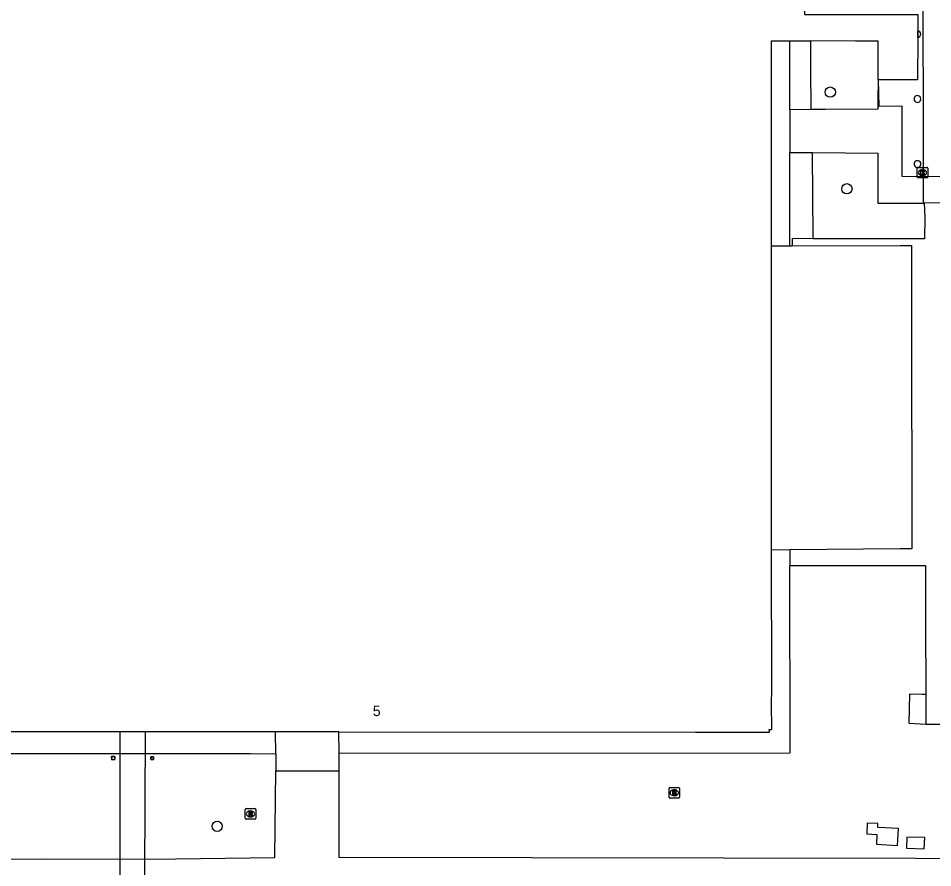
# Model space of a CAD drawing. Extents: x 161477 to 163040, y 383680 to 384868.
# Drawn here: x 161935.3 to 162022.7, y 384190.1 to 384271.2 of the extents above; entities that cross this region are included whole.
import ezdxf

# ---------------------------------------------------------------- set-up
doc = ezdxf.new("R2010")
doc.units = 0
for name, color, linetype in [('IMGEO_Boom', 7, 'Continuous'), ('IMGEO_Dek', 7, 'Continuous'), ('IMGEO_Groenvoorziening', 7, 'Continuous'), ('IMGEO_Kolk', 7, 'Continuous'), ('IMGEO_Pand', 7, 'Continuous'), ('IMGEO_Pand_nummerreeks', 7, 'Continuous'), ('IMGEO_Pand_overbouw', 7, 'Continuous'), ('IMGEO_Pijler', 7, 'Continuous'), ('IMGEO_Rijbaan_lokaal_open', 7, 'Continuous'), ('IMGEO_Rioolput', 7, 'Continuous'), ('IMGEO_Voetpad_gesloten', 7, 'Continuous'), ('IMGEO_Voetpad_op_trap', 7, 'Continuous'), ('IMGEO_Voetpad_open', 7, 'Continuous')]:
    doc.layers.add(name, color=color, linetype=linetype)

msp = doc.modelspace()

# ---------------------------------------------------------------- linework, layer by layer
at = {"layer": 'IMGEO_Boom'}
for centre in [(162012.875, 384264.123), (162014.462, 384254.892), (161954.33, 384194.04)]:
    msp.add_circle(centre, 0.489, dxfattribs=at)
at = {"layer": 'IMGEO_Dek'}
msp.add_lwpolyline([(161947.489, 384203.069), (161945.033, 384203.068), (161945.027, 384175.873), (161947.367, 384175.873)], close=True, dxfattribs=at)
at = {"layer": 'IMGEO_Groenvoorziening'}
for points in [[(162009.013, 384262.435), (162009.005, 384268.839), (162009.005, 384269.016)], [(162010.976, 384269.004), (162010.991, 384266.446), (162011.013, 384262.446)], [(162009.028, 384249.462), (162009.028, 384250.61), (162009.018, 384258.358)], [(162011.256, 384250.13), (162011.254, 384250.328), (162011.163, 384258.196), (162011.161, 384258.345)], [(161965.971, 384201.033), (162009.044, 384201.043), (162009.028, 384218.951)], [(161944.549, 384200.403), (161944.256, 384200.397), (161944.25, 384200.69), (161944.543, 384200.696), (161944.549, 384200.403)], [(161947.99, 384200.678), (161948.263, 384200.679), (161948.264, 384200.406), (161947.991, 384200.405), (161947.99, 384200.678)]]:
    msp.add_lwpolyline(points, dxfattribs=at)
at = {"layer": 'IMGEO_Kolk'}
for p, q in [((162021.174, 384256.011), (162021.174, 384256.863)), ((162021.249, 384256.937), (162022.101, 384256.937)), ((162022.175, 384256.863), (162022.175, 384256.011)), ((162022.101, 384255.937), (162021.249, 384255.937)), ((162021.685, 384256.157), (162021.66, 384256.157)), ((162021.662, 384256.717), (162021.687, 384256.717))]:
    msp.add_line(p, q, dxfattribs=at)
for points in [[(162021.174, 384256.011), (162021.174, 384256.863)], [(162021.249, 384256.937), (162022.101, 384256.937)], [(162022.175, 384256.863), (162022.175, 384256.011)], [(162022.101, 384255.937), (162021.249, 384255.937)], [(162021.495, 384256.637), (162021.618, 384256.637), (162021.618, 384256.486), (162021.748, 384256.637), (162021.912, 384256.637), (162021.766, 384256.486), (162021.919, 384256.237), (162021.767, 384256.237), (162021.682, 384256.401), (162021.618, 384256.334), (162021.618, 384256.237), (162021.495, 384256.237), (162021.495, 384256.637)]]:
    msp.add_lwpolyline(points, dxfattribs=at)
for centre, start, end in [((162021.251, 384256.861), 91.55205, 178.44795), ((162021.251, 384256.861), 91.55205, 178.44795), ((162022.099, 384256.861), 1.55205, 88.44795), ((162022.099, 384256.861), 1.55205, 88.44795), ((162021.251, 384256.013), 181.55205, 268.44795), ((162021.251, 384256.013), 181.55205, 268.44795), ((162022.099, 384256.013), 271.55205, 358.44795), ((162022.099, 384256.013), 271.55205, 358.44795)]:
    msp.add_arc(centre, 0.0765, start, end, dxfattribs=at)
for centre, major_axis, ratio, start_param, end_param in [((162021.661, 384256.437), (-0.387, 0.002), 0.722429, 4.712389, 7.853982), ((162021.686, 384256.437), (-0.39, 0.002), 0.717154, 1.570796, 4.712389)]:
    msp.add_ellipse(centre, major_axis=major_axis, ratio=ratio, start_param=start_param, end_param=end_param, dxfattribs=at)
at = {"layer": 'IMGEO_Pand'}
for points in [[(162010.435, 384272.775), (162010.425, 384271.541), (162021.222, 384271.531), (162021.226, 384269.972)], [(162021.227, 384269.341), (162021.226, 384269.972)], [(162007.258, 384249.461), (162007.258, 384250), (162007.266, 384269.027), (162009.005, 384269.016)], [(162009.005, 384269.016), (162010.976, 384269.004)], [(162017.446, 384265.289), (162017.441, 384268.979), (162015.281, 384268.977), (162010.976, 384269.004)], [(162021.227, 384269.341), (162021.217, 384265.294), (162017.446, 384265.289)], [(161959.912, 384203.067), (161949.955, 384203.074), (161947.489, 384203.069), (161945.033, 384203.068), (161931.102, 384203.074), (161931.103, 384235.656), (161931.102, 384250), (161931.102, 384256.645)], [(162007.274, 384220.411), (162007.274, 384221.561), (162007.272, 384231.847), (162007.271, 384234.348), (162007.275, 384235.638), (162007.254, 384239.224), (162007.258, 384249.461)], [(161965.955, 384203.063), (162000, 384203.041), (162007.059, 384203.036), (162007.048, 384203.271), (162007.278, 384203.271), (162007.275, 384205.765), (162007.278, 384207.107), (162007.274, 384220.411)], [(161965.955, 384203.063), (161959.912, 384203.067)]]:
    msp.add_lwpolyline(points, dxfattribs=at)
for centre, radius, start, end in [((162021.207, 384269.656), 0.316, 0.1609, 86.46973), ((162021.208, 384269.655), 0.315, 273.39798, 0.34551), ((162021.195, 384263.457), 0.324, 77.16041, 359.98209), ((162021.197, 384263.458), 0.322, 359.74617, 77.39633), ((162021.204, 384257.25), 0.324, 77.04938, 0.04807), ((162021.201, 384257.248), 0.326, 0.35111, 76.74634)]:
    msp.add_arc(centre, radius, start, end, dxfattribs=at)
at = {"layer": 'IMGEO_Pand_overbouw'}
msp.add_lwpolyline([(162037.084, 384281.639), (162019.702, 384281.634), (162019.636, 384272.78), (162010.435, 384272.775), (162010.425, 384271.541), (162021.222, 384271.531), (162021.226, 384269.972), (162021.227, 384269.341), (162021.217, 384265.294), (162017.446, 384265.289), (162017.5, 384262.782), (162019.699, 384262.817), (162019.714, 384256.084), (162058.456, 384256.073)], dxfattribs=at)
at = {"layer": 'IMGEO_Pijler'}
for points in [[(161944.543, 384200.696), (161944.25, 384200.69), (161944.256, 384200.397), (161944.549, 384200.403)], [(161948.263, 384200.679), (161947.99, 384200.678), (161947.991, 384200.405), (161948.264, 384200.406)]]:
    msp.add_lwpolyline(points, close=True, dxfattribs=at)
at = {"layer": 'IMGEO_Rijbaan_lokaal_open'}
for points in [[(162021.765, 384253.534), (162021.759, 384279.548)], [(162021.765, 384253.534), (162021.847, 384253.534)], [(162027.95, 384253.54), (162027.77, 384253.54), (162021.847, 384253.534)]]:
    msp.add_lwpolyline(points, dxfattribs=at)
at = {"layer": 'IMGEO_Rioolput'}
for p, q in [((161997.479, 384196.814), (161997.479, 384197.666)), ((161997.554, 384197.74), (161998.406, 384197.74)), ((161997.967, 384197.52), (161997.992, 384197.52)), ((161998.48, 384197.666), (161998.48, 384196.814)), ((161998.406, 384196.74), (161997.554, 384196.74)), ((161997.99, 384196.96), (161997.965, 384196.96)), ((161957.009, 384194.804), (161957.009, 384195.656)), ((161957.084, 384195.73), (161957.936, 384195.73)), ((161958.01, 384195.656), (161958.01, 384194.804)), ((161957.52, 384194.95), (161957.495, 384194.95)), ((161957.497, 384195.51), (161957.522, 384195.51)), ((161957.936, 384194.73), (161957.084, 384194.73))]:
    msp.add_line(p, q, dxfattribs=at)
for points in [[(161997.479, 384196.814), (161997.479, 384197.666)], [(161997.554, 384197.74), (161998.406, 384197.74)], [(161998.068, 384197.438), (161997.816, 384197.44), (161997.816, 384197.04)], [(161998.48, 384197.666), (161998.48, 384196.814)], [(161998.406, 384196.74), (161997.554, 384196.74)], [(161997.816, 384197.04), (161997.94, 384197.04), (161997.94, 384197.202), (161997.951, 384197.202)], [(161997.994, 384197.359), (161997.94, 384197.359), (161997.94, 384197.278)], [(161997.94, 384197.278), (161997.992, 384197.278)], [(161997.998, 384197.173), (161998.069, 384197.04), (161998.209, 384197.04), (161998.144, 384197.166)], [(161957.009, 384194.804), (161957.009, 384195.656)], [(161957.084, 384195.73), (161957.936, 384195.73)], [(161958.01, 384195.656), (161958.01, 384194.804)], [(161957.598, 384195.428), (161957.346, 384195.43), (161957.346, 384195.03)], [(161957.346, 384195.03), (161957.47, 384195.03), (161957.47, 384195.192), (161957.481, 384195.192)], [(161957.524, 384195.349), (161957.47, 384195.349), (161957.47, 384195.268)], [(161957.47, 384195.268), (161957.522, 384195.268)], [(161957.528, 384195.163), (161957.599, 384195.03), (161957.739, 384195.03), (161957.674, 384195.156)], [(161957.936, 384194.73), (161957.084, 384194.73)]]:
    msp.add_lwpolyline(points, dxfattribs=at)
for centre, radius, start, end in [((161997.556, 384197.664), 0.0765, 91.55205, 178.44795), ((161997.556, 384197.664), 0.0765, 91.55205, 178.44795), ((161998.067, 384197.328), 0.109, 350.36119, 89.41601), ((161998.404, 384197.664), 0.0765, 1.55205, 88.44795), ((161998.404, 384197.664), 0.0765, 1.55205, 88.44795), ((161997.556, 384196.816), 0.0765, 181.55205, 268.44795), ((161997.556, 384196.816), 0.0765, 181.55205, 268.44795), ((161997.95, 384197.149), 0.0533, 26.02933, 88.69889), ((161997.976, 384197.467), 0.19, 274.7715, 282.96867), ((161998, 384197.263), 0.0964, 77.00612, 93.18647), ((161998.014, 384197.32), 0.0378, 276.66336, 79.67722), ((161998.065, 384197.328), 0.112, 277.58423, 350.98172), ((161998.049, 384197.113), 0.108, 29.51342, 73.79051), ((161998.404, 384196.816), 0.0765, 271.55205, 358.44795), ((161998.404, 384196.816), 0.0765, 271.55205, 358.44795), ((161957.086, 384195.654), 0.0765, 91.55205, 178.44795), ((161957.086, 384195.654), 0.0765, 91.55205, 178.44795), ((161957.934, 384195.654), 0.0765, 1.55205, 88.44795), ((161957.934, 384195.654), 0.0765, 1.55205, 88.44795), ((161957.086, 384194.806), 0.0765, 181.55205, 268.44795), ((161957.086, 384194.806), 0.0765, 181.55205, 268.44795), ((161957.48, 384195.139), 0.0533, 26.02933, 88.69889), ((161957.506, 384195.457), 0.19, 274.7715, 282.96867), ((161957.53, 384195.253), 0.0964, 77.00612, 93.18647), ((161957.544, 384195.31), 0.0378, 276.66336, 79.67722), ((161957.597, 384195.318), 0.109, 350.36119, 89.41601), ((161957.595, 384195.318), 0.112, 277.58423, 350.98172), ((161957.579, 384195.103), 0.108, 29.51342, 73.79051), ((161957.934, 384194.806), 0.0765, 271.55205, 358.44795), ((161957.934, 384194.806), 0.0765, 271.55205, 358.44795)]:
    msp.add_arc(centre, radius, start, end, dxfattribs=at)
for centre, major_axis, ratio, start_param, end_param in [((161997.966, 384197.24), (-0.387, 0.002), 0.722429, 4.712389, 7.853982), ((161997.991, 384197.24), (-0.39, 0.002), 0.717154, 1.570796, 4.712389), ((161957.496, 384195.23), (-0.387, 0.002), 0.722429, 4.712389, 7.853982), ((161957.521, 384195.23), (-0.39, 0.002), 0.717154, 1.570796, 4.712389)]:
    msp.add_ellipse(centre, major_axis=major_axis, ratio=ratio, start_param=start_param, end_param=end_param, dxfattribs=at)
at = {"layer": 'IMGEO_Voetpad_gesloten'}
for points in [[(161947.489, 384203.069), (161945.033, 384203.068), (161945.027, 384175.873), (161947.367, 384175.873), (161947.489, 384203.069)], [(162019.382, 384193.822), (162017.411, 384193.93), (162017.41, 384194.302), (162016.402, 384194.337), (162016.351, 384193.332), (162017.326, 384193.248), (162017.289, 384192.353), (162019.287, 384192.209), (162019.382, 384193.822)], [(162021.892, 384192.965), (162020.194, 384193.006), (162020.161, 384191.95), (162021.838, 384191.899), (162021.892, 384192.965)]]:
    msp.add_lwpolyline(points, dxfattribs=at)
at = {"layer": 'IMGEO_Voetpad_op_trap'}
for points in [[(161965.971, 384201.033), (161965.955, 384203.063)], [(161959.929, 384200.954), (161959.935, 384200.23), (161959.943, 384199.331)], [(161965.985, 384199.331), (161965.973, 384200.793), (161965.971, 384201.033)]]:
    msp.add_lwpolyline(points, dxfattribs=at)
at = {"layer": 'IMGEO_Voetpad_open'}
for points in [[(162017.446, 384265.289), (162017.425, 384263.395), (162017.428, 384262.781), (162017.43, 384262.482), (162012.43, 384262.454), (162011.013, 384262.446)], [(162011.013, 384262.446), (162009.013, 384262.435)], [(162009.013, 384262.435), (162009.018, 384258.358)], [(162009.018, 384258.358), (162011.161, 384258.345)], [(162011.161, 384258.345), (162017.415, 384258.307), (162017.43, 384253.533), (162021.765, 384253.534)], [(162021.847, 384253.534), (162021.898, 384252.146), (162021.863, 384250.123), (162011.256, 384250.13)], [(162011.256, 384250.13), (162009.225, 384250.131), (162009.222, 384249.636), (162009.221, 384249.462)], [(162007.258, 384249.461), (162008.391, 384249.461), (162009.028, 384249.462)], [(162009.221, 384249.462), (162019.558, 384249.47), (162020.638, 384249.471), (162020.645, 384243.286), (162020.669, 384220.523), (162019.563, 384220.514), (162009.027, 384220.426)], [(162009.028, 384249.462), (162009.221, 384249.462)], [(162009.027, 384220.426), (162007.274, 384220.411)], [(162009.027, 384220.426), (162009.028, 384218.951)], [(161901.724, 384190.932), (161901.724, 384218.997), (161928.988, 384218.997), (161928.988, 384200.994), (161945.032, 384200.994), (161947.488, 384200.994), (161957.522, 384200.994), (161959.929, 384200.954)], [(162009.028, 384218.951), (162021.659, 384218.951), (162021.965, 384218.951), (162021.976, 384213.59), (162021.99, 384206.625)], [(162021.99, 384206.625), (162021.657, 384206.63), (162020.453, 384206.649), (162020.382, 384203.901), (162021.995, 384203.805)], [(162021.99, 384206.625), (162021.995, 384203.805)], [(162021.995, 384203.805), (162022.138, 384203.805), (162029.625, 384203.8), (162029.664, 384197.71), (162029.597, 384194.691), (162036.663, 384194.685), (162036.69, 384190.945)], [(161959.929, 384200.954), (161959.912, 384203.067)], [(161901.724, 384190.932), (161937.431, 384190.919), (161950.369, 384190.922), (161959.829, 384191.078), (161959.943, 384199.331)], [(161959.943, 384199.331), (161965.812, 384199.331), (161965.985, 384199.331)], [(162036.69, 384190.945), (162021.037, 384190.964), (161965.965, 384191.055), (161965.985, 384199.331)]]:
    msp.add_lwpolyline(points, dxfattribs=at)

# ---------------------------------------------------------------- texts
at = {"layer": 'IMGEO_Pand_nummerreeks'}
msp.add_text('5', height=1, rotation=359.95989, dxfattribs=at).set_placement((161969.191, 384204.561))

doc.saveas('drawing.dxf')
